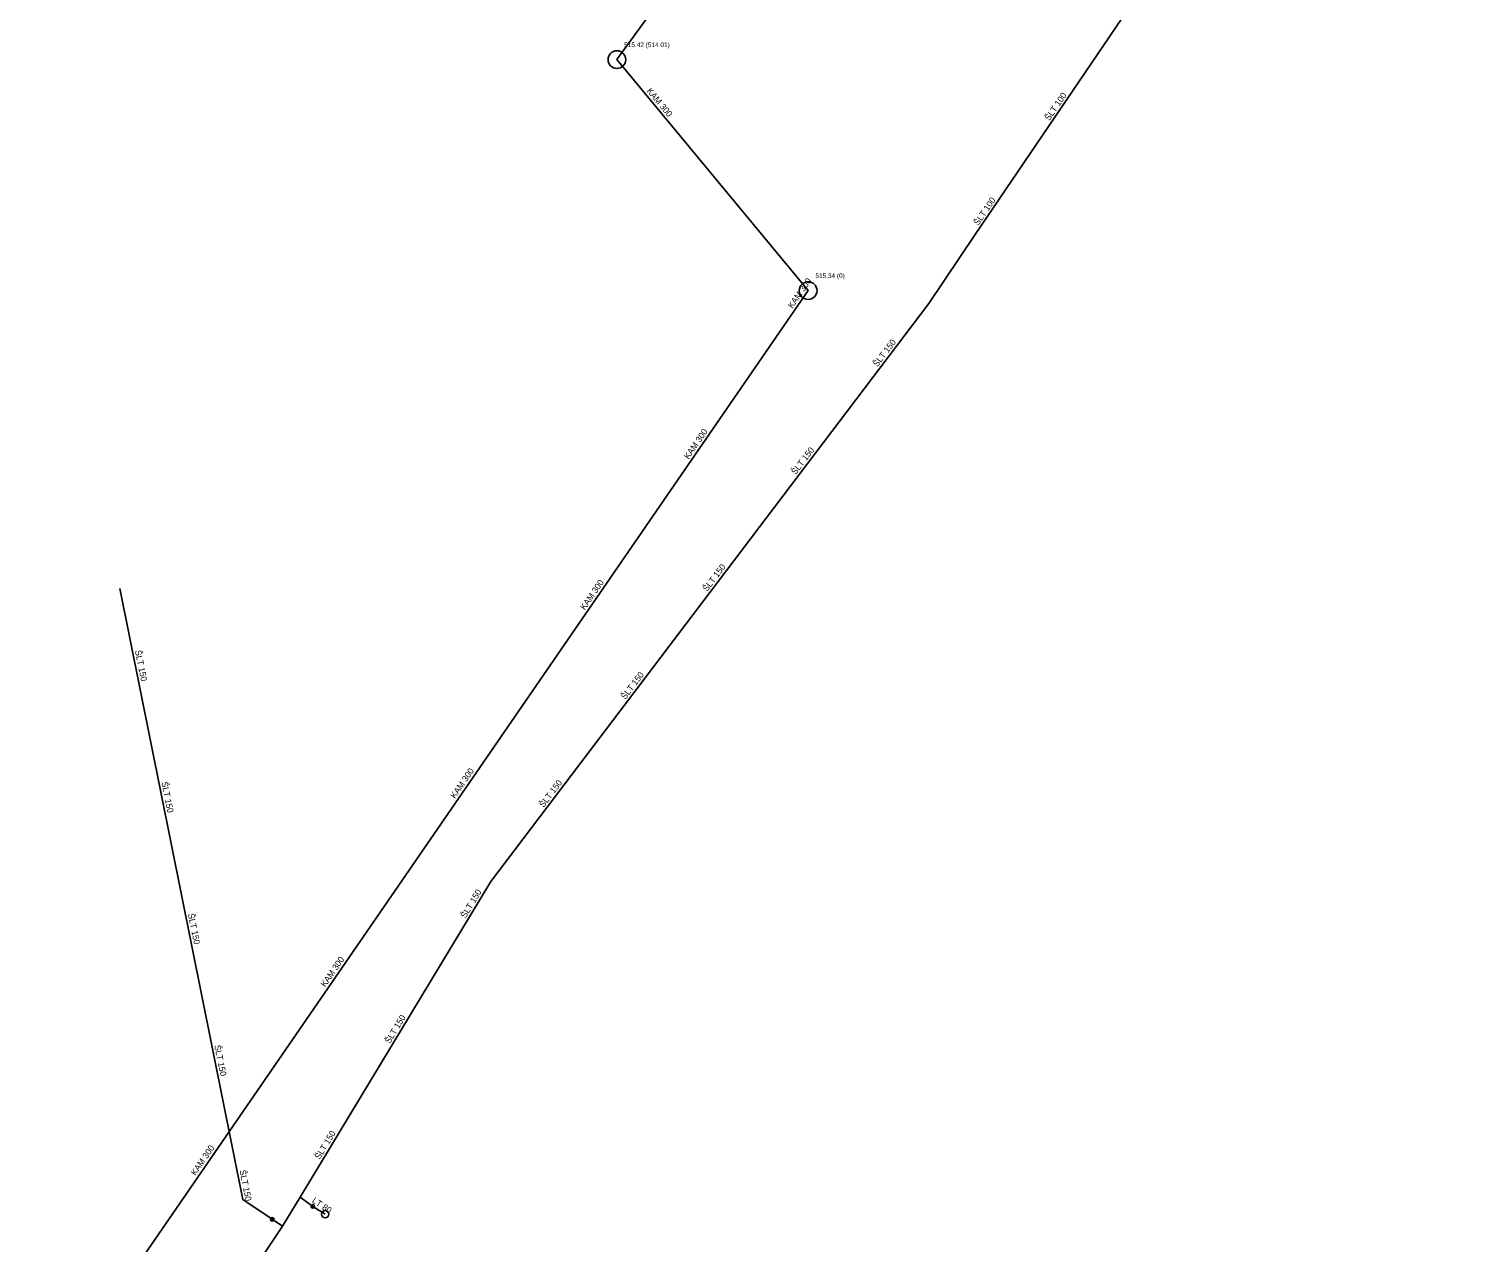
# Model space of a CAD drawing. Extents: x -668995 to -668929, y -1128059 to -1127935.
# Drawn here: x -668988.07 to -668947.09, y -1128031.61 to -1127997.4 of the extents above; entities that cross this region are included whole.
import ezdxf

# ---------------------------------------------------------------- set-up
doc = ezdxf.new("R2010")
doc.units = 0
for name, color, linetype in [('hydrant_o', 7, 'Continuous'), ('JEDN_D', 7, 'Continuous'), ('k_sachta_clip_Layer', 7, 'Continuous'), ('k_sachta_clip_LayerAnotace', 7, 'Continuous'), ('k_sachta_o', 7, 'Continuous'), ('kanal_clip_LayerAnotace', 7, 'Continuous'), ('soupe_o', 7, 'Continuous'), ('VOD_D', 7, 'Continuous'), ('VOD_O', 7, 'Continuous'), ('vodovod_clip_LayerAnotace', 7, 'Continuous')]:
    doc.layers.add(name, color=color, linetype=linetype)

msp = doc.modelspace()

# ---------------------------------------------------------------- linework, layer by layer
at = {"layer": 'hydrant_o'}
msp.add_circle((-668979.724, -1128030.802), 0.1, dxfattribs=at)
at = {"layer": 'JEDN_D'}
for p, q in [((-668971.5, -1127998.26), (-668961.347, -1127984.22)), ((-668966.11, -1128004.77), (-668971.5, -1127998.26)), ((-668988.06, -1128036.65), (-668966.11, -1128004.77))]:
    msp.add_line(p, q, dxfattribs=at)
at = {"layer": 'k_sachta_clip_Layer'}
for p, q in [((-668971.5, -1127998.26), (-668971.5, -1127998.26)), ((-668966.11, -1128004.77), (-668966.11, -1128004.77))]:
    msp.add_line(p, q, dxfattribs=at)
at = {"layer": 'k_sachta_o'}
for centre in [(-668971.5, -1127998.26), (-668966.11, -1128004.77)]:
    msp.add_circle(centre, 0.25, dxfattribs=at)
at = {"layer": 'soupe_o'}
for centre in [(-668980.07, -1128030.582), (-668981.216, -1128030.945)]:
    msp.add_circle(centre, 0.05, dxfattribs=at)
at = {"layer": 'VOD_D'}
msp.add_lwpolyline([(-668962.706, -1128005.131), (-668961.399, -1128003.191), (-668951.762, -1127988.985), (-668947.09, -1127982.604), (-668947.139, -1127981.212), (-668949.061, -1127979.903), (-668957.851, -1127973.916), (-668958.425, -1127973.525)], dxfattribs=at)
at = {"layer": 'VOD_O'}
msp.add_line((-668975.05, -1128021.427), (-668962.706, -1128005.131), dxfattribs=at)
for points in [[(-668980.925, -1128031.139), (-668981.216, -1128030.945), (-668982.048, -1128030.39), (-668985.511, -1128013.168)], [(-668975.05, -1128021.427), (-668980.433, -1128030.326), (-668980.925, -1128031.139)], [(-668980.433, -1128030.326), (-668980.07, -1128030.582), (-668979.724, -1128030.802)], [(-668980.925, -1128031.139), (-668985.463, -1128037.947), (-668988.07, -1128041.858), (-668986.656, -1128045.686), (-668982.53, -1128048.35), (-668966.644, -1128059.489)]]:
    msp.add_lwpolyline(points, dxfattribs=at)

# ---------------------------------------------------------------- texts
at = {"layer": 'k_sachta_clip_LayerAnotace'}
for s, height, p in [('515.42 (514.01)', 0.13163, (-668971.295, -1127997.907)), ('515.34 (0)', 0.1316, (-668965.905, -1128004.417))]:
    msp.add_text(s, height=height, dxfattribs=at).set_placement(p)
at = {"layer": 'kanal_clip_LayerAnotace'}
for rotation, p in [(309.6236, (-668970.672, -1127999.149)), (55.4518, (-668966.552, -1128005.288)), (55.4521, (-668969.479, -1128009.538)), (55.4517, (-668972.405, -1128013.788)), (55.4517, (-668976.063, -1128019.101)), (55.4517, (-668979.721, -1128024.414)), (55.4519, (-668983.379, -1128029.727))]:
    msp.add_text('KAM 300', height=0.1755, rotation=rotation, dxfattribs=at).set_placement(p)
at = {"layer": 'vodovod_clip_LayerAnotace'}
for s, rotation, p in [('ŠLT 100', 55.869, (-668959.311, -1127999.997)), ('ŠLT 100', 55.869, (-668961.312, -1128002.949)), ('ŠLT 150', 52.8568, (-668964.159, -1128006.932)), ('ŠLT 150', 52.8569, (-668966.463, -1128009.973)), ('ŠLT 150', 52.857, (-668968.958, -1128013.268)), ('ŠLT 150', 281.3678, (-668985.086, -1128014.922)), ('ŠLT 150', 52.857, (-668971.262, -1128016.309)), ('ŠLT 150', 281.3679, (-668984.34, -1128018.631)), ('ŠLT 150', 52.857, (-668973.566, -1128019.351)), ('ŠLT 150', 58.8294, (-668975.765, -1128022.472)), ('ŠLT 150', 281.3679, (-668983.594, -1128022.341)), ('ŠLT 150', 58.8295, (-668977.904, -1128026.009)), ('ŠLT 150', 281.368, (-668982.849, -1128026.05)), ('ŠLT 150', 58.8294, (-668979.879, -1128029.273)), ('ŠLT 150', 281.368, (-668982.14, -1128029.573)), ('LT 80', 326.1221, (-668980.112, -1128030.457))]:
    msp.add_text(s, height=0.1755, rotation=rotation, dxfattribs=at).set_placement(p)

doc.saveas('drawing.dxf')
